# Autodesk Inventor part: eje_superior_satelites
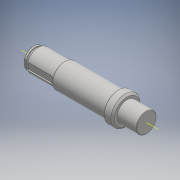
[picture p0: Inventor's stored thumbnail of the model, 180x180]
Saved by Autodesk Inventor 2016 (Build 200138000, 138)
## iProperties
Created: 2016-10
Part Number: eje_superior_satelites
Material: Generic
Document SubType Name: Modeling
Designer: Ingenieria
Density: 1 g/cm^3
Appearance: Default
Author: Ingenieria
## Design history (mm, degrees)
sketch "Sketch1"
  geometry: C1 r 32.5 at (0, 0); 1 further point
  constraints: 1 centre point, 1 coincident
  dimensions: "d0" = 65 diameter of C1
extrude "Extrusion1" new body sketch "Sketch1" stored distance "d1" = 255; taper "d2" = 0 deg
sketch "Sketch2"
  geometry: C1 r 22.5 at (0, 0); C2 r 32.5 at (0, 0); 1 further point
  constraints: 2 centre point, 2 coincident
  dimensions: "d3" = 45 diameter of C1; "d4" = 65 diameter of C2
extrude "Extrusion2" cut sketch "Sketch2" distance "d5" = 44; taper "d6" = 0 deg
sketch "Sketch3"
  geometry: C1 r 27.5 at (0, 0); C2 r 32.5 at (0, 0); 1 further point
  constraints: 2 centre point, 2 coincident
  dimensions: "d7" = 55 diameter of C1; "d8" = 65 diameter of C2
extrude "Extrusion3" cut sketch "Sketch3" distance "d9" = 191; taper "d10" = 0 deg
sketch "Sketch4"
  geometry: C1 r 25 at (0, 0); C2 r 27.5 at (0, 0) reference; C3 r 27.5 at (0, 0); 1 further point
  constraints: 2 centre point, 2 coincident
  dimensions: "d11" = 50 diameter of C1; "d12" = 55 diameter of C3
extrude "Extrusion4" cut sketch "Sketch4" distance "d13" = 70; taper "d14" = 0 deg
workplane "Work Plane1"
sketch "Sketch5"
  geometry: C1 r 20 at (0, 0); C2 r 25 at (0, 0); 1 further point
  constraints: 2 centre point, 2 coincident
  dimensions: "d16" = 40 diameter of C1; "d17" = 50 diameter of C2
extrude "Extrusion5" cut sketch "Sketch5" distance "d18" = 5.5; taper "d19" = 0 deg
sketch "Sketch6"
  geometry: C1 r 22.5 at (0, 0); C2 r 25 at (0, 0); 1 further point
  constraints: 2 centre point, 2 coincident
  dimensions: "d20" = 45 diameter of C1; "d21" = 50 diameter of C2
extrude "Extrusion6" cut sketch "Sketch6" stored distance "d22" = 5.5; taper "d23" = 0 deg
workplane "Work Plane2"
sketch "Sketch7"
  geometry: L1 (0, 8)-(-62, 8); L2 (0, -8)-(-62, -8); L3 (-70, 8)-(-70, -8); L4 (-70, -25)-(-70, 25) reference; L5 (0, 8)-(0, -8); A1 r 8 centre (-62, 0) between (-62, 8) and (-62, -8); 2 further points
  constraints: 8 end point, 3 tangent, 2 point on circle, 1 centre point, 1 collinear, 1 horizontal, 1 parallel, 1 vertical
  dimensions: "d28" = 8 radius of A1; "d31" = 17 distance from line of point (-10, 25) L1; "d33" = 0 distance from line of L3.start L1; "d34" = 16 distance from line of L3.end L1; "d55" = 70 distance between parallel lines of L5 L4; "d56" = 0 distance between parallel lines of L3 L4
extrude "Extrusion7" cut sketch "Sketch7" distance "d35" = 4; taper "d36" = 0 deg
chamfer "Chamfer1" distance "d37" = 1; stored, may be unused: second distance "d38" = 2, angle "d39" = 45 deg
chamfer "Chamfer2" distance "d40" = 1; stored, may be unused: second distance "d41" = 2, angle "d42" = 45 deg
chamfer "Chamfer3" distance "d43" = 1; stored, may be unused: second distance "d44" = 2, angle "d45" = 45 deg
chamfer "Chamfer4" distance "d46" = 1; stored, may be unused: second distance "d47" = 2, angle "d48" = 45 deg
chamfer "Chamfer5" distance "d49" = 1; stored, may be unused: second distance "d50" = 2, angle "d51" = 45 deg
chamfer "Chamfer6" distance "d52" = 4; stored, may be unused: second distance "d53" = 2, angle "d54" = 45 deg
body "Solid1"
